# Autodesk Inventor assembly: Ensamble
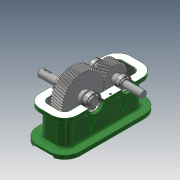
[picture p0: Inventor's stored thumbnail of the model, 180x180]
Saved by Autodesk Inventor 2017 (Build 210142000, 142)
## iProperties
Created: 2019-02
Part Number: Ensamble
Document SubType Name: Assembly
Designer: user
Author: user
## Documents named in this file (13)
- C:\Users\user\Documents\EIA\Cursos\Diseño asistido por computador\Clase 7 Dynamic simulation\Ensamble reductor de velocidad\Ensamble.iam
- C:\Users\user\Documents\EIA\Cursos\Diseño asistido por computador\Clase 7 Dynamic simulation\Ensamble reductor de velocidad\GearBox.ipt
- C:\Users\user\Documents\EIA\Cursos\Diseño asistido por computador\Clase 7 Dynamic simulation\Ensamble reductor de velocidad\Ensamble\Design Accelerator\Shaft1.iam
- C:\Users\user\Documents\EIA\Cursos\Diseño asistido por computador\Clase 7 Dynamic simulation\Ensamble reductor de velocidad\Ensamble\Design Accelerator\Bearing1.iam
- C:\Users\user\Documents\EIA\Cursos\Diseño asistido por computador\Clase 7 Dynamic simulation\Ensamble reductor de velocidad\Ensamble\Design Accelerator\Bearing2.iam
- C:\Users\user\Documents\EIA\Cursos\Diseño asistido por computador\Clase 7 Dynamic simulation\Ensamble reductor de velocidad\Ensamble\Design Accelerator\Shaft2.iam
- C:\Users\user\Documents\EIA\Cursos\Diseño asistido por computador\Clase 7 Dynamic simulation\Ensamble reductor de velocidad\Ensamble\Design Accelerator\Bearing3.iam
- C:\Users\user\Documents\EIA\Cursos\Diseño asistido por computador\Clase 7 Dynamic simulation\Ensamble reductor de velocidad\Ensamble\Design Accelerator\Bearing4.iam
- C:\Users\user\Documents\EIA\Cursos\Diseño asistido por computador\Clase 7 Dynamic simulation\Ensamble reductor de velocidad\GearBoxCover.ipt
- C:\Users\user\Documents\EIA\Cursos\Diseño asistido por computador\Clase 7 Dynamic simulation\Ensamble reductor de velocidad\GlassCover.ipt
- C:\Users\user\Documents\Inventor\Content Center Files\R2017\en-US\ANSI B 27.7M(2)\ANSI B 27.7M - 3AMI-17.ipt
- C:\Users\user\Documents\Inventor\Content Center Files\R2017\en-US\ANSI B 27.7M(2)\ANSI B 27.7M - 3AMI-20.ipt
- C:\Users\user\Documents\EIA\Cursos\Diseño asistido por computador\Clase 7 Dynamic simulation\Ensamble reductor de velocidad\Ensamble\Design Accelerator\Spur Gears1.iam
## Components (14 placed, 8 different names)
1. GearBox:1 — Insert:1, Insert:2, Mate:5, Flush:5, Flush:6
2. Shaft:1 [sub-assembly] — Insert:1, Mate:1, Flush:1, Mate:2, Flush:2, Insert:3, Insert:4, Mate:6, Mate:7, Angle:2
3. Bearing:1 [sub-assembly] — Mate:1, Flush:1
4. Bearing:2 [sub-assembly] — Mate:2, Flush:2
5. Shaft:2 [sub-assembly] — Insert:2, Mate:3, Flush:3, Mate:4, Flush:4, Insert:5, Insert:6, Mate:8, Mate:9, Angle:1
6. Bearing:3 [sub-assembly] — Mate:3, Flush:3
7. Bearing:4 [sub-assembly] — Mate:4, Flush:4
8. GearBoxCover:1 — Mate:5, Flush:5, Flush:6, Flush:7
9. GlassCover:1 — Flush:7
10. ANSI B 27.7M 3AMI-17:1 — Insert:3
11. ANSI B 27.7M 3AMI-17:2 — Insert:4
12. ANSI B 27.7M 3AMI-20:1 — Insert:5
13. ANSI B 27.7M 3AMI-20:2 — Insert:6
14. Spur Gears:1 [sub-assembly] — Mate:6, Mate:7, Mate:8, Mate:9, Angle:1, Angle:2
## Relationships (24: Mate 9, Flush 7, Insert 6, Angle 2)
- Insert:1: GearBox:1 ↔ Shaft:1
- Mate:1: Shaft:1 ↔ Bearing:1
- Flush:1: Shaft:1 ↔ Bearing:1
- Mate:2: Shaft:1 ↔ Bearing:2
- Flush:2: Shaft:1 ↔ Bearing:2
- Insert:2: GearBox:1 ↔ Shaft:2
- Mate:3: Shaft:2 ↔ Bearing:3
- Flush:3: Shaft:2 ↔ Bearing:3
- Mate:4: Shaft:2 ↔ Bearing:4
- Flush:4: Shaft:2 ↔ Bearing:4
- Mate:5: GearBox:1 ↔ GearBoxCover:1
- Flush:5: GearBox:1 ↔ GearBoxCover:1
- Flush:6: GearBox:1 ↔ GearBoxCover:1
- Flush:7: GearBoxCover:1 ↔ GlassCover:1
- Insert:3: Shaft:1 ↔ ANSI B 27.7M 3AMI-17:1
- Insert:4: Shaft:1 ↔ ANSI B 27.7M 3AMI-17:2
- Insert:5: Shaft:2 ↔ ANSI B 27.7M 3AMI-20:1
- Insert:6: Shaft:2 ↔ ANSI B 27.7M 3AMI-20:2
- Mate:6: Shaft:1 ↔ Spur Gears:1
- Mate:7: Shaft:1 ↔ Spur Gears:1
- Mate:8: Shaft:2 ↔ Spur Gears:1
- Mate:9: Shaft:2 ↔ Spur Gears:1
- Angle:1: Shaft:2 ↔ Spur Gears:1
- Angle:2: Shaft:1 ↔ Spur Gears:1
